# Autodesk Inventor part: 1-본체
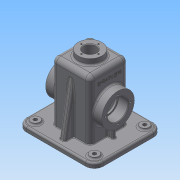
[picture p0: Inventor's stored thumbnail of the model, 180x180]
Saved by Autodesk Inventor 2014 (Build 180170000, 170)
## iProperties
Created: 2015-12
Part Number: 1-본체
Material: Generic
Document SubType Name: Modeling
Designer: Administrator
Density: 1 g/cm^3
Appearance: Default
Author: Administrator
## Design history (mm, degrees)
sketch "스케치1"
  geometry: L1 (50, -57.5)-(-50, -57.5); L2 (-65, -42.5)-(-65, 42.5); L3 (-50, 57.5)-(50, 57.5); L4 (65, 42.5)-(65, -42.5); L5 (65, -57.5)-(-65, 57.5); L6 (-65, -57.5)-(65, 57.5); A1 r 15 centre (-50, 42.5) between (-50, 57.5) and (-65, 42.5); A2 r 15 centre (-50, -42.5) between (-65, -42.5) and (-50, -57.5); A3 r 15 centre (50, -42.5) between (50, -57.5) and (65, -42.5); A4 r 15 centre (50, 42.5) between (65, 42.5) and (50, 57.5); 1 further point
  constraints: 12 end point, 8 point on circle, 8 point on line, 8 tangent, 4 centre point, 3 equal radius, 2 midpoint, 2 parallel, 1 horizontal, 1 perpendicular
  dimensions: "d0" = 115 distance of L6.start L5.end; "d1" = 130 distance of L5.end L6.end; "d2" = 15 radius of A1
extrude "돌출1" new body sketch "스케치1" distance "d3" = 10; taper "d4" = 0 deg
sketch "스케치2"
  geometry: L1 (24.5, -32.5)-(-24.5, -32.5); L2 (-32.5, -24.5)-(-32.5, 24.5); L3 (-24.5, 32.5)-(24.5, 32.5); L4 (32.5, 24.5)-(32.5, -24.5); L5 (32.5, -32.5)-(-32.5, 32.5); L6 (-32.5, -32.5)-(32.5, 32.5); A1 r 8 centre (-24.5, 24.5) between (-24.5, 32.5) and (-32.5, 24.5); A2 r 8 centre (24.5, 24.5) between (32.5, 24.5) and (24.5, 32.5); A3 r 8 centre (24.5, -24.5) between (24.5, -32.5) and (32.5, -24.5); A4 r 8 centre (-24.5, -24.5) between (-32.5, -24.5) and (-24.5, -32.5); 1 further point
  constraints: 12 end point, 8 point on circle, 8 point on line, 8 tangent, 4 centre point, 3 equal radius, 2 midpoint, 2 parallel, 1 horizontal, 1 perpendicular
  dimensions: "d5" = 65 distance of L5.end L6.end; "d6" = 65 distance of L6.start L5.end; "d7" = 8 radius of A1
extrude "돌출2" join sketch "스케치2" distance "d8" = 100; taper "d9" = 0 deg
sketch "스케치3"
  geometry: L1 (50, 57.5)-(-50, 57.5) reference; L2 (-65, 42.5)-(-65, -42.5) reference; L3 (-50, -57.5)-(50, -57.5) reference; L4 (65, -42.5)-(65, 42.5) reference; L5 (-50, 52.5)-(50, 52.5); L6 (60, 42.5)-(60, -42.5); L7 (50, -52.5)-(-50, -52.5); L8 (-60, -42.5)-(-60, 42.5); A1 r 15 centre (-50, 42.5) between (-50, 57.5) and (-65, 42.5) reference; A2 r 15 centre (-50, -42.5) between (-65, -42.5) and (-50, -57.5) reference; A3 r 15 centre (50, -42.5) between (50, -57.5) and (65, -42.5) reference; A4 r 15 centre (50, 42.5) between (65, 42.5) and (50, 57.5) reference; A5 r 10 centre (50, 42.5) between (60, 42.5) and (50, 52.5); A6 r 10 centre (50, -42.5) between (50, -52.5) and (60, -42.5); A7 r 10 centre (-50, -42.5) between (-60, -42.5) and (-50, -52.5); A8 r 10 centre (-50, 42.5) between (-50, 52.5) and (-60, 42.5); 1 further point
  constraints: 8 end point, 8 point on circle, 4 centre point, 7 other
  dimensions: "d10" = 5 distance between parallel lines of L2 L8
extrude "돌출3" cut sketch "스케치3" distance "d11" = 2; taper "d12" = 0 deg
node "작업 평면1"
sketch "스케치4"
  geometry: L1 (0, 85)-(0, 0) reference; L2 (0, 0)-(0, -15) reference; L3 (0, 100)-(0, 85) reference; L4 (0, 10)-(-100, 10) reference; L5 (0, -5)-(-85.069, 10); L6 (8, -15)-(0, -15) reference; L7 (0, 75)-(-100, 75) reference; L8 (-85.069, 10)-(-85.069, 75); L9 (-85.069, 75)-(0, 90); L10 (8, 100)-(0, 100) reference; 1 further point
  constraints: 6 end point, 4 point on line, 1 perpendicular
  dimensions: "d15" = 10 distance of L3.start L9.end; "d16" = 10 deg angle of L9 L10; "d17" = 10 deg angle of L5 L6
extrude "돌출4" join sketch "스케치4" stored distance "d18" = 10; taper "d19" = 0 deg
sketch "스케치5"
  geometry: L1 (24.5, -27.5)-(-24.5, -27.5); L2 (-27.5, -24.5)-(-27.5, 24.5); L3 (-24.5, 27.5)-(24.5, 27.5); L4 (27.5, 24.5)-(27.5, -24.5); L5 (27.5, -27.5)-(-27.5, 27.5); L6 (-27.5, -27.5)-(27.5, 27.5); A1 r 3 centre (-24.5, 24.5) between (-24.5, 27.5) and (-27.5, 24.5); A2 r 3 centre (24.5, 24.5) between (27.5, 24.5) and (24.5, 27.5); A3 r 3 centre (24.5, -24.5) between (24.5, -27.5) and (27.5, -24.5); A4 r 3 centre (-24.5, -24.5) between (-27.5, -24.5) and (-24.5, -27.5); 1 further point
  constraints: 12 end point, 8 point on circle, 8 point on line, 8 tangent, 4 centre point, 3 equal radius, 2 midpoint, 2 parallel, 1 horizontal, 1 perpendicular
  dimensions: "d20" = 55 distance of L5.end L6.end; "d21" = 55 distance of L6.start L5.end; "d22" = 3 radius of A1
extrude "돌출5" cut sketch "스케치5" distance "d23" = 105; taper "d24" = 0 deg
sketch "스케치6"
  geometry: C1 r 20 at (0, 0); 1 further point
  constraints: 1 centre point, 1 coincident
  dimensions: "d25" = 40 diameter of C1
extrude "돌출6" join sketch "스케치6" distance "d26" = 10; taper "d27" = 0 deg
node "작업 평면2"
sketch "스케치7"
  geometry: L1 (10, 67)-(10, -18) reference; L2 (8, -18)-(8, 67) reference; C1 r 27.5 at (-45, 24.5); 2 further points
  constraints: 1 centre point, 1 horizontal alignment, 1 midpoint
  dimensions: "d29" = 55 diameter of C1; "d31" = 55 distance from line of L1 C1.centre
extrude "돌출7" join sketch "스케치7" stored distance "d32" = 10; taper "d33" = 0 deg
hole "구멍1" diameter "d36" = 30; stored, may be unused: countersink angle "d40" = 90 deg, drill point angle "d42" = 118 deg; dims "d37" = 6, "d38" = 35, "d39" = 17, "d41" = 8, "d43" = 10, "d44" = 10
sketch "스케치8"
  geometry: C1 r 17.5 at (0, 0) reference; C2 r 27.5 at (0, 0) reference; A1 r 21 centre (0, 0) between (0, -21) and (-21, 0); 3 further points
  constraints: 4 point on circle, 2 horizontal alignment, 2 vertical alignment, 1 centre point, 1 coincident
  dimensions: "d45" = 42 diameter of A1
hole "구멍2" sketch "스케치8" at (0, -21), (-21, 0), (0, 21), (21, 0) diameter "d46" = 3.242; stored, may be unused: countersink angle "d50" = 90 deg, drill point angle "d52" = 118 deg; dims "d47" = 8, "d48" = 42, "d49" = 17, "d51" = 10
hole "구멍3" diameter "d55" = 21; stored, may be unused: countersink angle "d59" = 90 deg, drill point angle "d61" = 118 deg; dims "d53" = 10, "d54" = 10, "d56" = 8, "d57" = 42, "d58" = 17, "d60" = 10
sketch "스케치9"
  geometry: C1 r 10.5 at (0, 0) reference; C2 r 20 at (0, 0) reference; A1 r 14.5 centre (0, 0) between (14.5, 0) and (0, 14.5); 2 further points
  constraints: 4 point on circle, 2 horizontal alignment, 2 vertical alignment, 1 centre point, 1 coincident
  dimensions: "d62" = 29 diameter of A1
hole "구멍4" sketch "스케치9" at (14.5, 0), (0, 14.5), (-14.5, 0), (0, -14.5) diameter "d63" = 2.459; stored, may be unused: countersink angle "d67" = 90 deg, drill point angle "d69" = 118 deg; dims "d64" = 7, "d65" = 4, "d66" = 2, "d68" = 9
sketch "스케치10"
  geometry: C1 r 7.5 at (-50, 42.5); C2 r 7.5 at (50, 42.5); C3 r 7.5 at (-50, -42.5); C4 r 7.5 at (50, -42.5); A1 r 15 centre (-50, 42.5) between (-50, 57.5) and (-65, 42.5) reference; A2 r 15 centre (-50, -42.5) between (-65, -42.5) and (-50, -57.5) reference; A3 r 15 centre (50, -42.5) between (50, -57.5) and (65, -42.5) reference; A4 r 15 centre (50, 42.5) between (65, 42.5) and (50, 57.5) reference; 1 further point
  constraints: 4 centre point, 4 coincident, 1 equal radius
  dimensions: "d70" = 15 diameter of C1; "d71" = 15 diameter of C2; "d72" = 15 diameter of C3
extrude "돌출8" join sketch "스케치10" distance "d73" = 3; taper "d74" = 0 deg
sketch "스케치11"
  geometry: C1 r 7.5 at (0, 0) reference; C2 r 7.5 at (100, 0) reference; C3 r 7.5 at (100, -85) reference; C4 r 7.5 at (0, -85) reference; 5 further points
  constraints: 4 coincident
hole "구멍5" sketch "스케치11" at (0, 0), (100, 0), (100, -85), (0, -85) diameter "d75" = 6; stored, may be unused: countersink angle "d79" = 90 deg, drill point angle "d81" = 118 deg; dims "d76" = 6, "d77" = 4, "d78" = 2, "d80" = 9
fillet "모깎기1" dims "d82" = 8
fillet "모깎기5" dims "d91" = 3
node "작업 평면4"
sketch "스케치13"
  geometry: L1 (17.5, 0)-(17.5, 32.51) reference; L2 (17.5, 17.5)-(2.5, 17.5) reference; L3 (100, 0)-(0, 0) reference; L4 (7.5, 19)-(7.5, 0); L5 (22.5, -10)-(22.5, 95) reference; L6 (7.5, 19)-(19.04, 19); L7 (19.04, 19)-(19.04, 0); 1 further point
  constraints: 6 end point, 3 perpendicular, 2 point on line
  dimensions: "d92" = 15 distance between parallel lines of L4 L5; "d93" = 11.54026 distance of L4.start L6.end; "d94" = 19 distance of L6.end L7.end
extrude "돌출10" join sketch "스케치13" stored distance "d95" = 6; taper "d96" = 0 deg
fillet "모깎기6" dims "d97" = 3
fillet "모깎기7" dims "d98" = 1
fillet "모깎기8" dims "d99" = 3
fillet "모깎기9" dims "d100" = 0.3
fillet "모깎기10" dims "d101" = 3
chamfer "모따기1" distance "d102" = 1; stored, may be unused: second distance "d103" = 2, angle "d104" = 45 deg
sketch "스케치14"
  geometry: L1 (-65, 20)-(-65, -20) reference; 3 further points
  constraints: 1 horizontal alignment, 1 midpoint, 1 other
  dimensions: "d105" = 26 distance of point (-39, 0) point (-65, 0)
feature "엠보싱1" sketch "스케치14" dims "d5" = 65, "d6" = 65, "d7" = 8, "d106" = 0.5, "d107" = 0
fillet "모깎기11" dims "d108" = 3
fillet "모깎기12" dims "d109" = 3
node "솔리드1"
mirror "대칭1"
mirror "대칭3"
other parameters: "d28" = 15
